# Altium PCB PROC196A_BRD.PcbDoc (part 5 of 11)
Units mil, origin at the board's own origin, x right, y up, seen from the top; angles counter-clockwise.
Board outline 3346.45 x 4921.26 mil, 8 copper layers (Top Layer, GND1, SIG1, PWR1, PWR2, SIG2, GND2, Bottom Layer), stack 54.534 mil thick; 736 components, 498 nets, 3030 pads, 1279 vias.
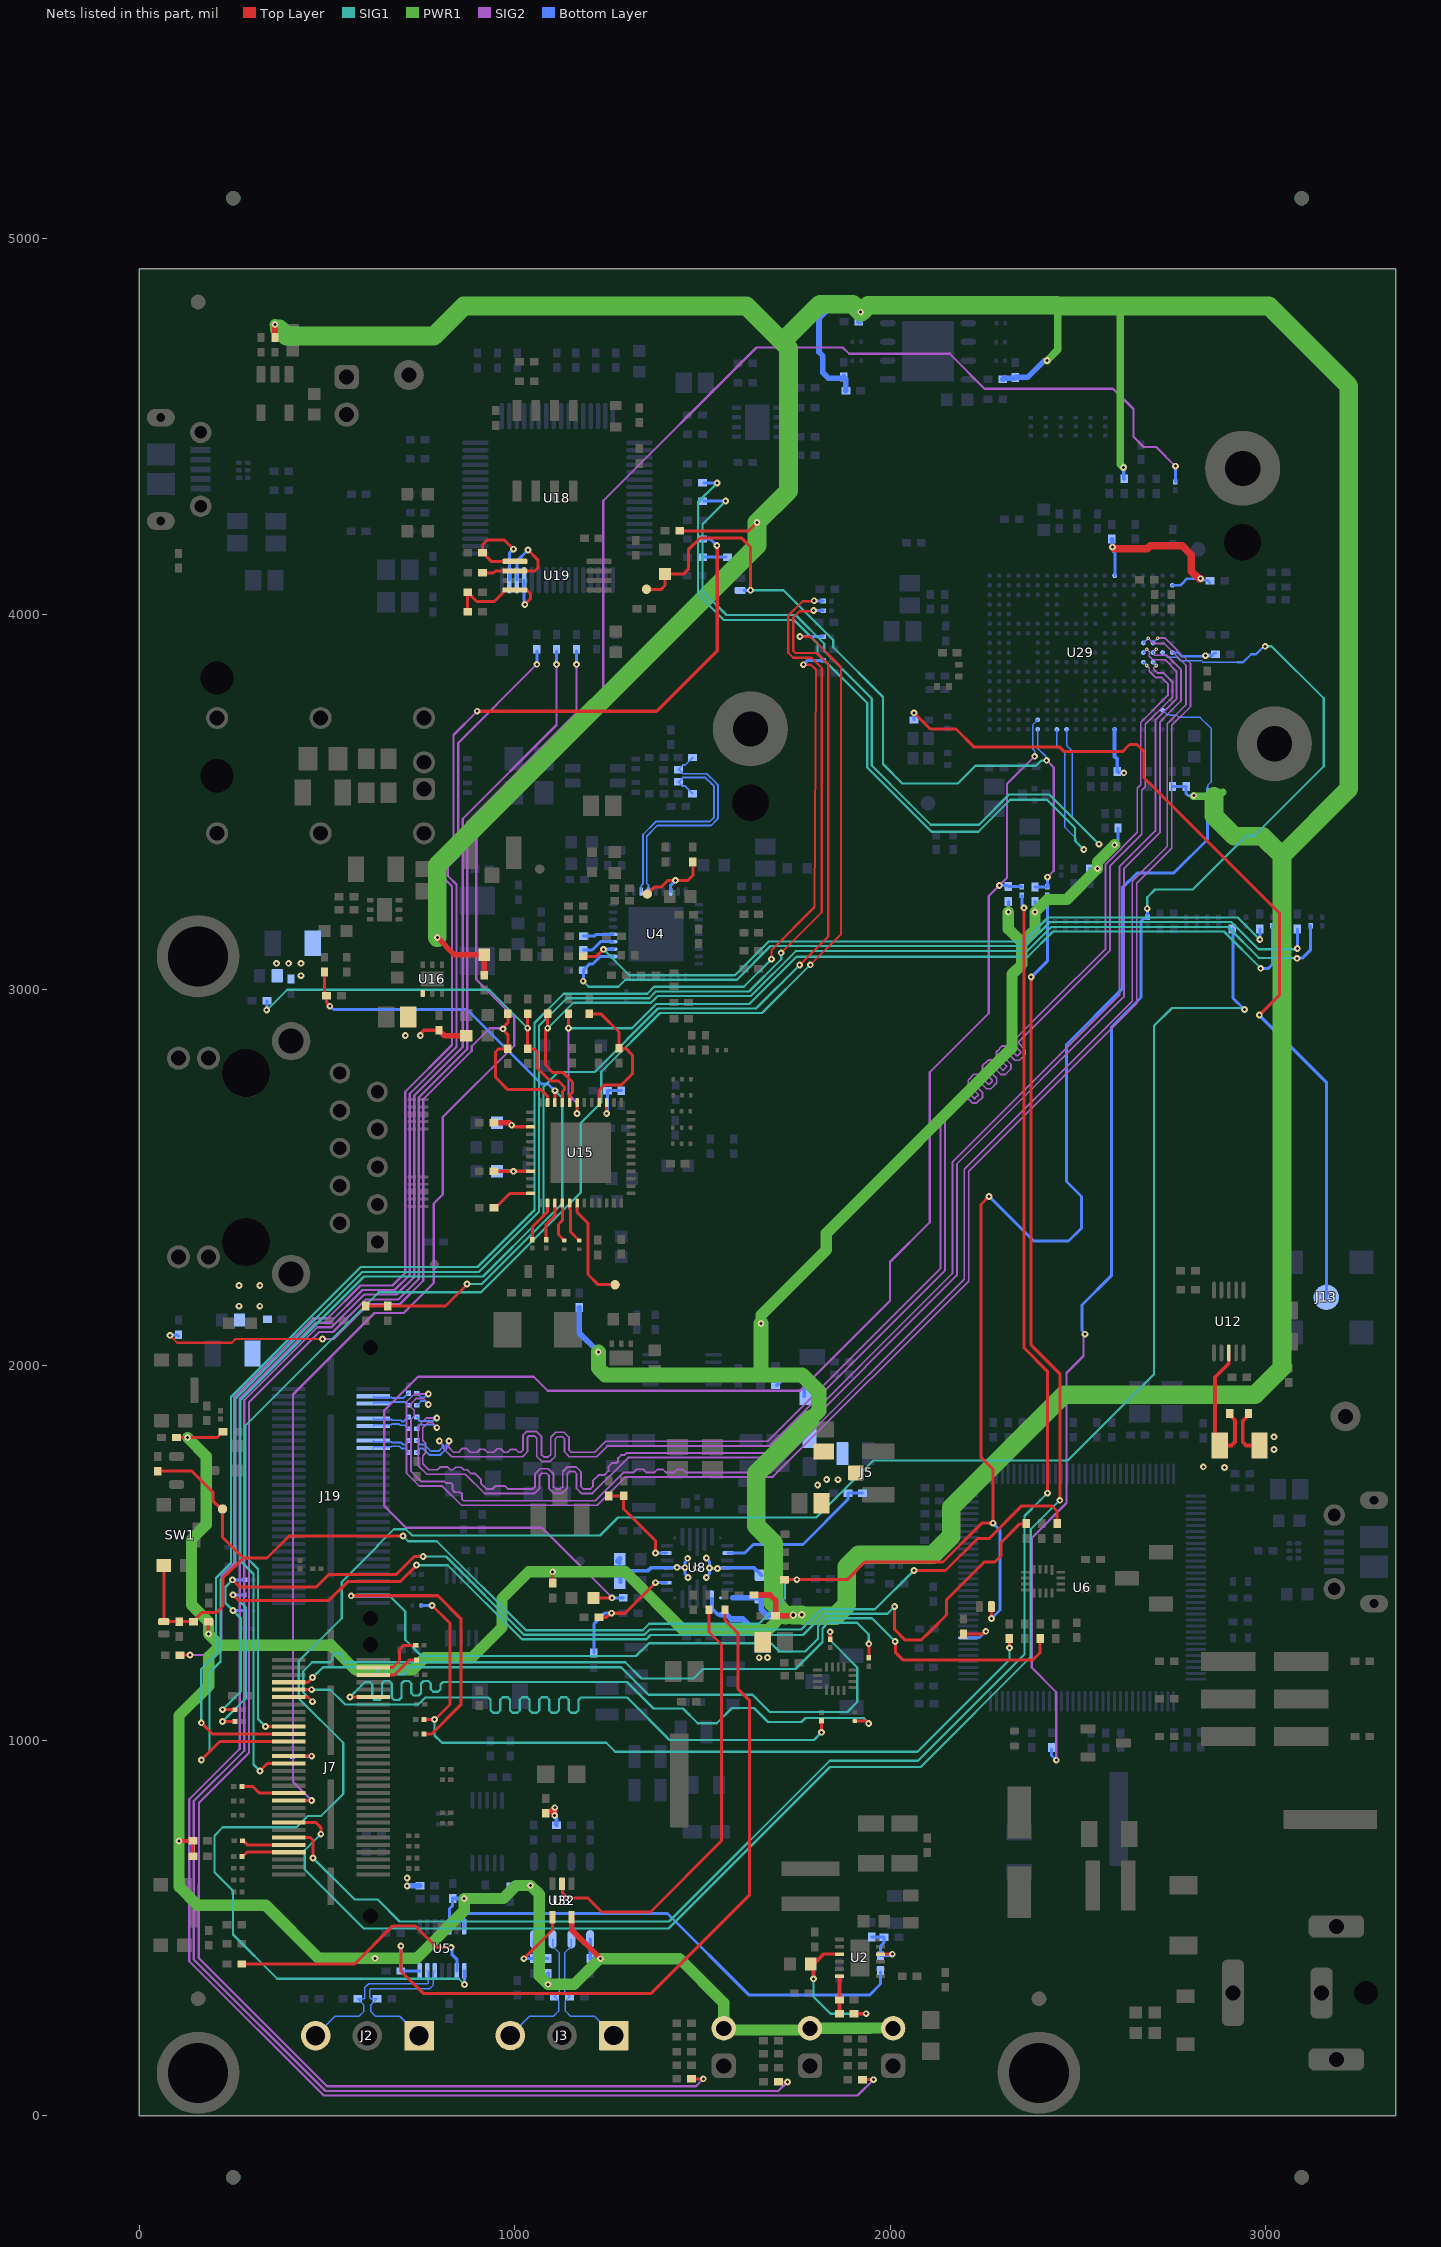
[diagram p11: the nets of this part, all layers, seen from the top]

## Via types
v1: diameter 18, hole 8, Top Layer to Bottom Layer, tented both sides, 1230 vias
v2: diameter 19.68, hole 7.87, Top Layer to Bottom Layer, 30 vias
v3: diameter 20, hole 10, Top Layer to Bottom Layer, tented both sides, 11 vias
v4: diameter 10, hole 4, SIG2 to Bottom Layer, tented both sides, 6 vias
v5: diameter 19.68, hole 7.87, Top Layer to Bottom Layer, tented both sides, 2 vias

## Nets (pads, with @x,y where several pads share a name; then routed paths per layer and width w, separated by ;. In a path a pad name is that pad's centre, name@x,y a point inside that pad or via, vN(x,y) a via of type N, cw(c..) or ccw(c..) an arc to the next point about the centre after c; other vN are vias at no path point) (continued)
1V8_FILTERED: C169.1 C194.1 C198.1 J5.1 R60.1 R65.1 R104.2 | length 114.6
  Bottom Layer w10: R65.1@1698.44,1946.4 1711.33,1959.29 1760.62,1959.29 1771.4,1948.52 R60.1@1771.4,1916.69
  other v1: 1807.21,1680.66 1831.14,1695.12 1861.42,1694.6
2V5_ETH: C34.1 C38.1 C59.1 C187.1 C188.1 C189.1 R293.2 U15.3 U15.9 U16.1 | length 398.4
  Top Layer w9: v1(991.92,2639.09) 994.36,2639.09 999.01,2634.44 U15.3@1042.07,2634.44 ; v1(997.01,2516.33) U15.9@1042.07,2516.33
  Top Layer w10: v1@748.4,2881.92 758.32,2891.84 C34.1@798.3,2891.84 ; C188.1@948.66,2516.33 v1(997.01,2516.33)
  Top Layer w15: C34.1@798.3,2891.84 812.92,2877.21 R293.2@870.42,2877.21 ; C189.1@944.72,2645.15 985.05,2645.15 991.11,2639.09 v1(991.92,2639.09)
  Bottom Layer w10: C59.1@956.53,2516.33 v1(997.01,2516.33) ; C187.1@956.53,2645.15 v1@987.04,2645.15
  other v1: 708.4,2877.92 748.4,2877.92
3V3: C174.2 C175.2 C176.2 C177.2 R346.2 R348.1 U12.8 U29.A14 U29.J20 U29.T20 U29.U14 | length 1163.4
  Top Layer w10: U12.8@2902.35,2032.4 2902.35,2004.12 2865.55,1967.32 2865.55,1794.63 2874.14,1786.04 R346.2@2878.07,1786.04 2909.57,1786.04 2918.92,1795.39 2918.92,1853.17 R348.1@2905.36,1866.74
  Top Layer w20: v1(2592.55,4179) 2596.55,4175 2684.82,4175 2692.82,4183 2777.85,4183 2802.7,4158.16 2802.7,4115.34 2823.04,4095 v1(2827.47,4095)
  Bottom Layer w6: U29.J20@2751.89,3898.25 2766.56,3898.25 2776.55,3888.26 2838.64,3888.26 v1(2840.2,3889.81) ; C176.2@2856.7,3890.12 2863.04,3896.46 C176.2@2868.04,3896.46
  Bottom Layer w7: v1(2592.55,4179) 2594.65,4176.9 2594.65,4167.2 2599.18,4162.68 2599.18,4138.07 2599.18,4127.7 2599.18,4104.17 U29.U14@2598,4102.99 ; U29.T20@2751.52,4077.38 2773.99,4077.38 2777.67,4081.06 2791.61,4095 2830.45,4095 2835.04,4090.41 2845.53,4090.41 C177.2@2851.87,4084.07
  Bottom Layer w10: U29.A14@2597.98,3693.52 2597.98,3621.48 2605.12,3614.33 C175.2@2605.12,3581.08 2606.68,3579.53 2621.25,3579.53 v1(2622.78,3578) ; v1@2840.5,3890.12 C176.2@2856.7,3890.12
  Bottom Layer w12: C174.2@2590.78,4200.46 2591.67,4199.57 2591.67,4179.88 v1(2592.55,4179)
  other v1: 2890.8,1727.02 2834.59,1728.9
3V3_VIO: C12.2 C20.2 J17.2 J18.2 J20.2 R18.1 R28.1 R37.1 R38.2 R41.2 R43.2 R49.2 R53.1 R106.2 R116.2 R177.1 R199.2 R261.2 R262.2 R263.2 R264.2 R271.2 R272.2 R273.2 R276.2 R277.2 R278.2 R279.2 R280.2 R295.2 R301.2 R309.2 R333.2 R346.1 R352.1 R409.2 U3.5 U5.5 U32.5 | length 21624.3
  Top Layer w8: R333.2@98.52,1807.13 v1(127.97,1807.13) 207.37,1807.13 R263.2@223.1,1822.86 ; R262.2@1100.93,1419.24 v1(1100.96,1449.11) ; R261.2@1439.69,4222.31 1623,4222.31 v1(1645.5,4244.81)
  Top Layer w10: v1(105.33,732.43) R276.2@142.44,732.43 R277.2@142.44,691.43 ; v1@183.82,1284.23 R264.2@183.82,1316.33 ; R352.1@2954.95,1866.86 2939.82,1851.73 2939.82,1794.25 2948.03,1786.04 R346.1@2978.54,1786.04
  Top Layer w15: R409.2@361.36,4737.7 v1(361.36,4772.2) ; v1(793.83,3138.78) 839.8,3092.81 R28.1@918.99,3092.81 R295.2@918.99,3038.71 ; U32.5@1151.52,529.29 1151.52,495.51 v1(1228.36,418.66) ; R106.2@1637.16,1387.47 1680.18,1387.47 1694.99,1372.67 R199.2@1694.99,1332.02 1738.38,1332.02 1740.36,1334 v3(1741.71,1334)
  PWR1 w20: v1(2418,4676) 2446.89,4704.89 2446.89,4821.18 ; 2612.88,4821.18 2612.88,4399.95 v1(2621.58,4391.26) ; v1@2806.98,3514.81 v1(2809.17,3517) 2811.36,3514.81 2862.65,3514.81 2874.11,3514.81 2886,3526.71
  PWR1 w30: v1(127.97,1807.13) 177.92,1757.17 177.92,1574.6 138.95,1535.63 138.95,1361.6 184.2,1316.35 v1(184.2,1283.85) 214.78,1253.27 ; v1(361.36,4772.2) 372.69,4760.87 ; v1(1656.27,2111) 1656.27,2132.75 1829.91,2306.39 1829.91,2350.9 2324.55,2845.54 2324.55,3041.23 2351,3067.68 2351,3125.86 ; 1721.25,1334 1714.41,1334 1675.41,1295 1448.69,1295 1294.59,1449.11 v1(1100.96,1449.11) 1037.1,1449.11 966.21,1378.22 966.21,1301.35 884.91,1220.05 759.41,1220.05 727.52,1188.16 576.21,1188.16 511.09,1253.27 214.78,1253.27 ; J20.2@2007.9,233.08 2007.9,233.71 1946.47,233.71 1945.84,233.08 1791.39,233.08 1786.64,228.34 1561.38,228.34 1556.83,232.88 J17.2@1556.83,233.08 1556.83,300.92 1439.08,418.66 v1(1228.36,418.66) 1226.72,418.66 1158.28,350.23 v1(1088.45,350.23) 1065.62,373.05 1065.62,590.2 v1(1042.17,613.65) 1003.93,613.65 969.36,579.09 v1(865.36,579.09) 865.36,546.41 738.48,419.53 v1(627.95,419.53) 478,419.53 336.72,560.81 155,560.81 105.33,610.48 v1(105.33,732.43) 105.33,1066.14 185,1145.81 185,1223.49 214.78,1253.27 ; v1(2314.95,3206.96) 2314.95,3161.92 2351,3125.86 ; v1(2598.26,3386) 2552.72,3340.46 v1(2552.72,3322.53) 2470.71,3240.52 2419.56,3240.52 v1(2386,3206.96) 2386,3160.86 2351,3125.86
  PWR1 w40: v1(1222.74,2034.89) 1222.74,1991.75 1240.3,1974.19 1656.27,1974.19 ; v1(1656.27,2111) 1656.27,1974.19 ; 1721.25,1334 v3(1741.71,1334) ; 1787.19,1854.76 1809.97,1877.54 1809.97,1929.65 1765.43,1974.19 1656.27,1974.19
  PWR1 w50: 372.69,4760.87 392.29,4741.26 784.23,4741.26 864.15,4821.18 1617.63,4821.18 1712.95,4725.86 ; v1(793.83,3138.78) 793.83,3331.64 1645.5,4183.31 v1(1645.5,4244.81) 1729.69,4329 1729.69,4709.12 1712.95,4725.86 ; 1721.25,1334 1689.65,1365.6 1689.65,1525.4 1643.23,1571.82 1643.23,1710.81 1787.19,1854.76 ; v3(1741.71,1334) 1763.95,1334 v3(1764.95,1335) 1767.93,1332.02 1855.05,1332.02 1884.34,1361.31 1884.34,1462.94 1916.08,1494.67 2113.3,1494.67 2162.88,1544.25 2162.88,1620.62 2463.26,1921 2972.19,1921 3044,1992.81 3044,3356.81 ; 2862.65,3514.81 2862.65,3463.24 2916.89,3409 2991.81,3409 3044,3356.81 ; 1712.95,4725.86 1813.09,4826 1900.61,4826 v1(1921.61,4805) 1923.43,4805 1942.09,4823.66 2444.41,4823.66 2446.89,4821.18 2612.88,4821.18 3009.63,4821.18 3222.15,4608.66 3222.15,3534.96 3044,3356.81
  Bottom Layer w8: U5.5@825.99,503.91 825.99,525.29 826.46,525.76 826.46,551.89 834.66,560.09 C12.2@834.66,579.09 ; v1@2314.95,3207.63 R271.2@2314.95,3235.34 ; v1(2386,3206.96) R272.2@2386,3234.67 ; v1(2598.26,3386) 2598.26,3388.71 2607.2,3397.65 2607.2,3430.39 R309.2@2607.16,3430.44 ; R279.2@2752.31,3541.71 R278.2@2788.54,3541.71 ; R278.2@2788.94,3541.2 2788.94,3522.32 2793.63,3517.63 2808.54,3517.63 v1(2809.17,3517)
  Bottom Layer w10: v1(627.95,419.53) R18.1@657.14,419.53 ; C12.2@834.66,579.09 v1(865.36,579.09) ; R53.1@987.9,613.65 v1(1042.17,613.65) ; v1(1088.45,350.23) R177.1@1088.45,379.29 ; U3.5@1200.93,470.24 C20.2@1200.93,418.66 v1(1228.36,418.66) ; R301.2@2531.76,3322.25 2532.04,3322.53 v1(2552.72,3322.53) ; v1(2621.58,4391.26) 2622.62,4390.22 2622.62,4362.14 R273.2@2623.66,4361.1
  Bottom Layer w15: R280.2@1171.49,2153.02 1171.49,2086.13 v1(1222.74,2034.89) ; R116.2@1713.65,1332.02 1714.67,1333.04 1740.75,1333.04 v3(1741.71,1334) ; R38.2@1882.26,4595.86 1882.26,4626.29 R49.2@1876.26,4632.29 1872.97,4629 1835.62,4629 1820.83,4643.79 1820.83,4688.34 1810.72,4698.45 1810.72,4787.96 1834.76,4812 1913.8,4812 1920.8,4805 v1(1921.61,4805) 1921.61,4804.19 1920.94,4803.52 1920.94,4781.63 1918.6,4779.29 R43.2@1916.63,4779.29 ; R37.1@2300.06,4626.23 2302.4,4628.58 2330.92,4628.58 2333.26,4630.92 R41.2@2333.26,4631.21 2366.04,4631.21 2410.25,4675.43 2417.43,4675.43 v1(2418,4676)
  other v1: 3023,1774.81 3023,1808.81
3V3REG_EN: R6.2 U5.7 | length 1275.1
  Bottom Layer w8: U5.7@865.36,503.91 865.36,533.17 871,538.81 1407.22,538.81 1624.52,321.51 1944.95,321.51 1974.33,350.89 R6.2@1974.33,383.23
3V3REG_ENA: R6.1 R7.2 R8.1 U2.10 | length 152
  Top Layer w8: U2.10@1974.33,430.47 v1(2005.93,430.47)
  Bottom Layer w8: R8.1@1950.73,476.14 R7.2@1984.19,476.14 1984.19,461.42 1974.33,451.56 R6.1@1974.33,426.54 2001.99,426.54 v1(2005.93,430.47)
3V3REG_MODE: R9.1 R10.2 U2.6 | length 99.7
  Top Layer w10: R9.1@1864.88,271.68 1864.88,285.53 R10.2@1864.88,308.55 U2.6@1864.88,371.42
3V3REG_VCC: C10.1 R9.2 U2.3 | length 357.8
  Top Layer w8: 1822.79,430.56 1823.02,430.78 1843.51,430.78 1843.51,430.47 U2.3@1864.88,430.47
  Top Layer w10: v1(1796.21,365.1) C10.1@1796.21,404.47 ; C10.1@1796.7,404.47 1822.79,430.56 1823.02,430.56 ; R9.2@1904.25,271.68 1935.92,271.68 v1(1936.33,272.1)
  SIG1 w6: v1(1796.21,365.1) 1796.21,317.38 1841.49,272.1 v1(1936.33,272.1)
5V0: C119.1 C120.1 R16.2 R78.2 R332.2 U8.10 | length 315
  Top Layer w15: R332.2@1082.76,806.12 1082.76,808.09 1085.1,810.43 1095.46,810.43 1106.03,821 v1(1106.84,821) ; v1(1106.32,800) 1106.84,800.52 v1@1106.84,815.96
  Bottom Layer w10: v1(1106.32,800) 1108.04,798.28 1108.04,796.49 1111.55,792.97 R78.2@1111.55,774.22 R78.2@1108.19,777.59 ; U8.10@1525.5,1376.58 1525.5,1350.98 1541.38,1335.1 1548.07,1335.1 ; C119.1@1660.85,1261.41 C119.1@1660.85,1270.18
  Bottom Layer w15: v1@715.7,612.55 R16.2@747.25,612.55 ; 1548.07,1335.1 1564.36,1335.1 1575.8,1323.66 1607.37,1323.66 C119.1@1660.85,1270.18
  other v1: 713.59,612.55 713.59,633.51 1651.19,1220.55 1673.49,1220.68
+3.3VD: C124.2 R116.1 U8.9 | length 132.6
  Bottom Layer w15: 1580.61,1379.84 1656.4,1379.84 C124.2@1657.09,1379.14 1657.09,1348.26 1673.33,1332.02 R116.1@1675.3,1332.02
AGND: C3.1 C123.1 C124.1 NT1.2 NT2.1 NT3.1 NT4.1 U8.5 U8.5-19 U8.19 | length 507.7
  Bottom Layer w8: U8.19@1409.35,1459.75 1410.05,1460.45 1431.63,1460.45 v1(1432.33,1461.15) 1432.64,1460.85 1452.63,1460.85 v1(1453.33,1460.15) ; v1(1460.93,1485.15) 1460.93,1483.03 1453.33,1475.43 v1(1453.33,1460.15) ; v1(1461.53,1434.35) 1461.53,1435.86 1453.33,1444.06 v1(1453.33,1460.15) ; v1(1510.53,1434.15) 1510.53,1435.46 1518.93,1443.86 v1(1518.93,1459.35) ; v1(1510.53,1485.95) 1510.53,1484.63 1518.93,1476.23 v1(1518.93,1459.35) ; U8.5@1562.9,1459.75 1562.2,1459.05 1540.62,1459.05 v1(1539.92,1458.35) 1539.61,1458.65 1519.62,1458.65 v1(1518.93,1459.35)
  Bottom Layer w10: C3.1@1279.98,1483.26 1279.98,1461.98 1289.6,1452.36 ; C123.1@1281.98,1421.26 1281.98,1444.73 1289.6,1452.36 ; U8.19@1409.35,1459.75 1362.77,1459.75 1355.38,1452.36 1289.6,1452.36 ; U8.5@1562.9,1459.75 1637.51,1459.75 C124.1@1657.09,1440.16
  Bottom Layer w15: C3.1@1274.74,1478.02 C3.1@1279.98,1483.26
  other v1: 1486.13,1459.75
AR_NERROUT: DS2.2 R76.1 R271.1 R379.1 U29.B6 | length 4317.2
  Top Layer w8: DS2.2@1210.1,1379.84 v1@1259.43,1379.84
  SIG2 w6: v1(1259.46,1379.87) 1072.47,1566.86 710.06,1566.86 652.44,1624.48 652.44,1879.25 742,1968.81 1051,1968.81 1088,1931.81 1759.75,1931.81 1999.5,2171.56 1999.5,2274.32 2105.57,2380.39 2105.57,2779.87 2262.76,2937.06 2262.76,3249.46 v1(2290.88,3277.57) 2291.09,3277.57 2311.7,3298.19 2311.7,3548.53 v1(2385.09,3621.93)
  Bottom Layer w4: v1(2385.09,3621.93) 2385.09,3636.13 2380.53,3640.69 2380.53,3706.39 U29.B6@2393.25,3719.11
  Bottom Layer w8: v1@1259.5,1379.84 R76.1@1289.24,1379.84 ; v1(2290.88,3277.57) 2291.13,3277.32 2312.34,3277.32 R271.1@2314.95,3274.71 2350.33,3274.71 R379.1@2351,3274.04
AR_NRST: C105.2 D2.2 D4.2 R99.1 R264.1 R266.1 SW1.4 TP4.1 U29.C19 | length 6359.5
  Top Layer w8: R266.1@49.46,1717.26 140.04,1717.26 196.49,1660.81 196.49,1637.49 221.49,1612.49 221.49,1541.07 276.57,1486 ; SW1.4@64.98,1452.25 D4.2@64.98,1316.33 C105.2@105.96,1316.33 R264.1@144.45,1316.33 144.45,1318.97 166.96,1341.47 205.94,1341.47 222.91,1358.44 222.91,1432.48 239.53,1449.11 239.68,1449.11 276.57,1486 ; v1(702.46,1544.91) 399.1,1544.91 340.19,1486 276.57,1486 ; v1(1751.63,1428.39) 1885.82,1428.39 1932.74,1475.31 2141.02,1475.31 2244.52,1578.81 v1(2274,1578.81) 2274,1722.16 2242,1754.16 2242,2427.69 v1(2263.73,2449.42) ; D2.2@2270.07,1356.5 2270.25,1356.32 v1(2270.25,1324.63)
  Top Layer w8.3: R99.1@1718.74,1428.39 v1(1751.63,1428.39)
  SIG1 w6: v1(702.46,1544.91) 716.37,1531 792.56,1531 1029.86,1293.7 1341.01,1293.7 1358.13,1310.81 1651.03,1310.81 1719.06,1378.85 1719.06,1415.5 1731.95,1428.39 v1(1751.63,1428.39)
  Bottom Layer w4: U29.C19@2725.93,3744.7 2738.76,3731.87 2746.36,3731.87 2746.4,3731.83 2763.15,3731.83 2769.48,3725.5 2825.77,3725.5 2854.95,3696.32 2854.95,3553.04 2845.65,3543.74 2845.65,3536.81
  Bottom Layer w8: v1(2263.73,2449.42) 2382.81,2330.34 2475.38,2330.34 2509.69,2364.66 2509.69,2449.35 2469.96,2489.08 2469.96,2853.77 2619.8,3003.61 2619.8,3273 2657.61,3310.81 2756,3310.81 2845.65,3400.46 2845.65,3536.81 ; v1(2270.25,1324.63) 2293,1347.38 2293,1559.81 v1(2274,1578.81)
AR_NRST_FTDI: R166.2 R268.1 | length 4018.4
  Top Layer w8: R268.1@108.28,1227 108.69,1227.4 134.59,1227.4 v1(135,1227.81)
  Top Layer w8.3: v1(899.92,3742.04) 900.15,3741.81 1378,3741.81 1539.43,3903.24 1539.43,4182.31 v1(1538.46,4183.28)
  SIG2 w6: v1(135,1227.81) 202.52,1227.81 219,1244.29 219,1438.81 252,1471.81 252,1913.39 463.42,2124.81 502.15,2124.81 589.34,2212 674.39,2212 708,2245.61 708,2727.88 833.08,2852.96 833.08,3275.33 809.69,3298.71 809.69,3336.55 836.62,3363.48 836.62,3678.74 v1(899.92,3742.04)
  Bottom Layer w8: R166.2@1503.74,4200.6 1521.14,4200.6 v1(1538.46,4183.28)
AR_NRST_XDS: R36.1 U6.40 | length 117.2
  Top Layer w7: R36.1@2194.69,1283.63 2245.4,1283.63 2252.58,1290.81 v1(2255,1290.81)
  Bottom Layer w7: U6.40@2208.34,1273.3 2208.5,1273.47 2236.8,1273.47 2254.14,1290.81 v1(2255,1290.81)
AR_SOP0_FTDI: R171.2 R308.2 | length 5983.6
  Top Layer w8: R308.2@1926.71,96.1 v1(1955.58,96.1)
  SIG2 w6: v1(1058.91,3867.06) 849.28,3657.43 849.28,3354.27 821.69,3326.68 821.69,3303.68 845.08,3280.3 845.08,2847.99 720,2722.91 720,2240.12 679.88,2200 594.31,2200 507.12,2112.81 468.96,2112.81 267.37,1911.22 267.37,977.7 133.19,843.52 133.19,411.62 491,53.81 1913.29,53.81 v1(1955.58,96.1)
  Bottom Layer w8: v1(1058.91,3867.06) R171.2@1058.91,3902.94
AR_SOP1_FTDI: R170.2 R304.2 | length 5720.1
  Top Layer w8: R304.2@1702.27,90.41 1702.43,90.25 1726.29,90.25 v1(1726.45,90.09)
  SIG2 w6: v1(1111.12,3867.06) 1111.12,3704.97 861.28,3455.13 861.28,2847.22 732,2717.94 732,2234.77 685.23,2188 599.28,2188 512.09,2100.81 473.93,2100.81 279.37,1906.25 279.37,972.73 145.19,838.55 145.19,416.59 495.97,65.81 1702.17,65.81 v1(1726.45,90.09)
  Bottom Layer w8: v1(1111.12,3867.06) R170.2@1111.12,3902.94
AR_SOP2_FTDI: R169.2 R298.2 | length 5496.8
  Top Layer w8: R298.2@1471.02,98.61 v1(1502.46,98.61)
  SIG2 w6: v1(1164.49,3867.06) 1164.49,3737.49 873.28,3446.28 873.28,2842.25 744,2712.97 744,2229.59 689.37,2174.96 603.21,2174.96 516.06,2087.81 479.31,2087.81 292.37,1900.86 292.37,967.18 237,911.81 236.84,911.81 159,833.97 159,615.81 158.19,615 158.19,420.56 499.94,78.81 1482.66,78.81 v1(1502.46,98.61)
  Bottom Layer w8: v1(1164.49,3867.06) R169.2@1164.49,3902.94
AR_WRMRST: D5.2 D9.2 R272.1 R371.1 TP1.1 U29.A6 | length 2145.8
  Top Layer w8: TP1.1@1351,4066.81 1390.5,4066.81 1400.32,4076.63 D9.2@1400.32,4107.81 1450.5,4107.81 1462.5,4119.81 1462.5,4171.81 1493.58,4202.89 1604.92,4202.89 1628.18,4179.63 v1(1628.18,4064.21)
  SIG1 w6: v1(1628.18,4064.21) 1715.84,4064.21 1848.39,3931.66 1848.39,3912.37 1980.93,3779.83 1980.93,3601.23 2032.61,3549.55 2180.22,3549.55 2227.53,3596.86 2236.05,3596.86 2236.1,3596.81 2388.95,3596.81 2402.55,3610.41 2416.37,3610.41 v1(2417.04,3611.07)
  SIG2 w6: v1(2417.04,3611.07) 2436,3592.11 2436,3316.67 v1(2419.01,3299.68)
  Bottom Layer w4: U29.A6@2393.25,3693.52 2393.25,3642.96 2414.48,3621.73 2414.48,3613.63 v1(2417.04,3611.07)
  Bottom Layer w8: D5.2@1610.48,4063.7 1610.74,4063.95 1627.93,4063.95 v1(1628.18,4064.21) ; R272.1@2386,3274.04 R371.1@2418.82,3274.04 2418.91,3274.14 2418.91,3299.59 v1(2419.01,3299.68)
AR_WRMRST_FTDI: R330.2 R362.1 | length 59.5
  Bottom Layer w8: R330.2@1503.76,4152.19 R362.1@1563.24,4152.19
BSS_UARTA_TX: R131.1 R232.2 U29.J19 | length 3811.4
  SIG1 w6: v1(2685,3215.81) 2685,3246.46 2705.54,3267 2806.6,3267 2949.75,3410.15 2969.9,3410.15 3154.97,3595.22 3154.97,3776.33 3016.3,3915 v1(2999.33,3915)
  SIG2 w6: v1(2442.69,947.36) 2442.69,1128.62 2377.21,1194.1 2377.21,1539.56 2470,1632.35 2470,1639.81 2470,1979.09 2515.14,2024.23 2515.14,2074.77 2519.29,2078.93 v1(2519.29,2082.18)
  Bottom Layer w4: U29.J19@2725.93,3898.25 2738.65,3885.52 2764.32,3885.52 2773.16,3876.68 2829.28,3876.68 2833.74,3872.23 2925.19,3872.23
  Bottom Layer w6: 2925.19,3872.23 2938.88,3872.23 2940.3,3872.23 2962.07,3894 2975.08,3894 2996.08,3915 v1(2999.33,3915)
  Bottom Layer w8: R131.1@2430.04,977.32 2430.04,960.01 v1(2442.69,947.36) ; v1(2519.29,2082.18) 2519.29,2083.85 2511.28,2091.86 2511.28,2159.87 2589.21,2237.8 2589.21,2899.64 2668.7,2979.13 2668.7,3182.41 2676.02,3189.72 2683.7,3189.72 2686,3192.02 R232.2@2686,3192.81 2685.5,3193.31 2685.5,3215.31 v1(2685,3215.81)
CAN_nFAULT: R233.2 U5.8 | length 5868.7
  SIG1 w6: v1(865.9,349.81) 850.89,364.82 367.56,364.82 249.37,483.01 249.37,599.69 200.05,649.01 200.05,746.31 222.15,768.42 418.6,768.42 449.22,799.04 484.31,799.04 542.87,857.6 542.87,993.98 424.81,1112.04 424.81,1211.62 539.04,1325.85 539.04,1421.86 635.02,1517.85 635.02,1519.9 678.03,1562.91 709.92,1562.91 726.83,1546 1227,1546 1275.1,1594.1 1803.34,1594.1 1955.05,1745.81 2473.46,1745.81 2703.33,1975.68 2703.33,2903.8 2751.04,2951.51 2936.23,2951.51 2940.73,2947 v1(2943.98,2947)
  Bottom Layer w8: U5.8@865.36,385.8 865.63,385.53 865.63,350.07 v1(865.9,349.81) ; R233.2@2912,3162.1 2913,3161.1 2913,2977.98 v1(2943.98,2947)
CAN_WAKE: R55.1 U5.9 | length 689.2
  Top Layer w8: R55.1@276.53,404.47 573.66,404.47 675.19,506 734.43,506 791.43,449 v1(830.65,449)
  Bottom Layer w8: v1(830.65,449) 832.56,447.09 832.56,430.22 845.68,417.1 U5.9@845.68,385.8
CANA_N: J3.1 R87.1 U3.6 | length 367
  Bottom Layer w4: U3.6@1150.93,470.24 1150.93,451.92 1132.68,433.67 1132.68,367.25 1132.68,327.75 1135.02,325.41 1138.53,325.41 R87.1@1146.38,317.57 1134.93,306.12 1134.93,279.07 1148.92,265.09 1212.45,265.09 J3.1@1263.73,213.81
CANA_NSTB: R13.1 U32.2 | length 1177.4
  Top Layer w8: U32.2@1125.93,617.88 1126.65,617.15 1126.65,594.17 1140.82,580 1194.84,580 1231.84,543 1361.42,543 1550.99,732.57 1550.99,1255.73 1517.62,1289.1 R13.1@1517.62,1348.1
CANA_P: J3.3 R85.2 U3.7 | length 367
  Bottom Layer w4: J3.3@988.14,213.81 1039.41,265.09 1102.94,265.09 1116.93,279.07 1116.93,306.13 R85.2@1105.49,317.57 1113.33,325.42 1116.84,325.42 1119.18,327.76 1119.18,360.5 1119.18,433.83 1100.93,452.08 U3.7@1100.93,470.24
CANA_STB: R86.1 R177.2 U3.8 U32.4 | length 258.2
  Top Layer w8: v1(1024.06,418.66) 1100.33,494.94 U32.4@1100.33,529.29
  Bottom Layer w8: v1(1024.06,418.66) R86.1@1050.93,418.66 ; U3.8@1050.93,470.24 R86.1@1050.93,418.66 ; R177.2@1088.45,418.66 R86.1@1050.93,418.66
CANB_N: J2.1 R24.1 U5.12 | length 451
  Bottom Layer w4: J2.1@745.14,213.43 693.48,265.09 629.21,265.09 616.34,277.95 616.34,295.36 R24.1@632.93,311.94 616.44,311.94 614.09,314.29 614.09,336.05 616.44,338.39 773.28,338.39 783.53,348.64 783.53,382.71 U5.12@786.62,385.8
CANB_NSTB: R17.1 R18.2 R19.1 U5.14 | length 2032.8
  Top Layer w8: v1(696.51,452.4) 696.51,385.8 756.16,326.16 1363.56,326.16 1624.94,587.54 1624.94,1106.89 1595.36,1136.47 1595.36,1285.11 1560.12,1320.35 R17.1@1560.12,1348.1
  Bottom Layer w8: v1(696.51,452.4) R18.2@696.51,419.53 R19.1@696.51,385.8 U5.14@747.25,385.8
CANB_P: J2.3 R15.2 U5.13 | length 451
  Bottom Layer w4: J2.3@469.55,213.43 521.21,265.09 585.48,265.09 598.34,277.95 598.34,295.36 R15.2@581.76,311.94 598.25,311.94 600.59,314.29 600.59,341.64 610.84,351.89 767.69,351.89 770.03,354.23 770.03,382.71 U5.13@766.94,385.8
CLKP_SMA: J13.1 R269.2 | length 2390.4
  Top Layer w8: v1(2063.49,3737.81) 2106.83,3694.47 2175.53,3694.47 2224,3646 2452.11,3646 2464.11,3634 2618.97,3634 2625,3640.03 2630,3645.03 2638.01,3653.04 2657.96,3653.04 2677,3634 2677,3564 2704.19,3536.81 3036.85,3204.15 3036.85,2985.6 v1(2983.58,2932.33)
  Bottom Layer w8: R269.2@2063.49,3718.43 v1(2063.49,3737.81) ; v1(2983.58,2932.33) 3162.24,2753.66 J13.1@3162.24,2180.42
CSI2_0_N: J19.58 R192.2 R196.1 | length 101
  Bottom Layer w4.8: J19.58@623.08,1916.88 626.18,1913.79 671.38,1913.79 673.03,1912.14 703.41,1912.14 716.08,1924.8 R196.1@716.86,1924.8
CSI2_0_P: J19.56 R191.2 | length 99.3
  Bottom Layer w4.8: J19.56@623.08,1897.19 626.18,1900.28 671.38,1900.28 673.03,1901.94 707.44,1901.94 716.08,1893.3 R191.2@716.86,1893.3
CSI2_1_N: J19.52 R189.2 | length 101.9
  Bottom Layer w4.8: J19.52@623.08,1857.82 626.18,1854.73 671.38,1854.73 673.03,1853.08 696.48,1853.08 699.55,1850.01 704.28,1850.01 716.08,1861.81 R189.2@716.86,1861.81
CSI2_1_P: J19.50 R168.2 | length 101
  Bottom Layer w4.8: J19.50@623.08,1838.14 626.18,1841.23 671.38,1841.23 673.03,1842.88 692.25,1842.88 695.32,1839.81 706.58,1839.81 716.08,1830.31 R168.2@716.86,1830.31
CSI2_CLK_N: J19.46 R138.2 | length 104.9
  Bottom Layer w4.8: J19.46@623.08,1798.77 626.18,1795.68 671.38,1795.68 673.03,1794.02 696.66,1794.02 702.51,1788.17 709.37,1788.17 712.18,1790.98 712.18,1794.92 716.08,1798.82 R138.2@716.86,1798.82
CSI2_CLK_P: J19.44 R135.2 | length 104.9
  Bottom Layer w4.8: J19.44@623.08,1779.08 626.18,1782.17 671.38,1782.17 673.03,1783.82 692.43,1783.82 698.29,1777.97 709.37,1777.97 712.18,1775.16 712.18,1771.22 716.08,1767.32 R135.2@716.86,1767.32
CSI2_RX0_0_N: R192.1 U29.K18 | length 4099.8
  SIG2 w4.8: v1(769.8,1923.05) 732.25,1923.05 711.58,1902.39 711.58,1712.26 746.33,1677.51 807.3,1677.51 858.09,1626.72 1219.85,1626.72 1295.35,1702.21 1687.78,1702.21 2209.37,2223.8 2209.37,2516.62 2657.16,2964.41 2657.16,3283.52 2750.31,3376.67 2750.31,3704.09 2800.37,3754.15 2800.37,3869.11 2734.74,3934.73 2732.84,3936.63 v4(2713.14,3936.63)
  Bottom Layer w4.8: R192.1@738.91,1924.8 739.7,1924.8 750.35,1914.15 760.39,1914.15 769.29,1923.05 v1(769.8,1923.05) ; U29.K18@2700.34,3923.84 v4(2713.14,3936.63)
CSI2_RX0_0_P: R191.1 U29.K17 | length 4101.6
  SIG2 w4.8: v1@769.69,1895.16 769.69,1898.35 756.99,1911.05 737.22,1911.05 723.58,1897.41 723.58,1888.16 732.05,1879.69 732.05,1864.29 723.58,1855.82 723.58,1717.23 751.3,1689.51 812.64,1689.51 816.29,1685.86 829.28,1685.86 834.13,1681.01 834.13,1668.02 840.7,1661.46 855.3,1661.46 859.26,1657.49 859.26,1642.9 863.44,1638.72 1214.88,1638.72 1290.38,1714.21 1317.24,1714.21 1325.25,1722.22 1341.7,1722.22 1349.71,1714.21 1372.4,1714.21 1380,1721.81 1395,1721.81 1402.6,1714.21 1425.29,1714.21 1432.89,1721.81 1447.89,1721.81 1455.49,1714.21 1682.81,1714.21 2197.37,2228.77 2197.37,2521.59 2645.16,2969.39 2645.16,3288.5 2738.31,3381.64 2738.31,3709.06 2788.37,3759.12 2788.37,3864.14 2729.77,3922.73 2701.45,3922.73 v4(2687.55,3936.63)
  Bottom Layer w4.8: R191.1@738.91,1893.3 739.7,1893.3 750.35,1903.95 760.39,1903.95 769.29,1895.05 v1(769.8,1895.05) ; U29.K17@2674.75,3923.84 v4(2687.55,3936.63)
CSI2_RX0_1_N: R189.1 U29.J18 | length 4092.4
  SIG2 w4.8: v1(792.39,1859.06) 764.26,1859.06 743,1837.8 743,1732.25 766.34,1708.91 868.71,1708.91 919.51,1658.12 1052.89,1658.12 1066.12,1671.35 1066.12,1705.7 1072.32,1711.9 1084.72,1711.9 1090.92,1705.7 1090.92,1671.35 1104.14,1658.12 1126.49,1658.12 1139.72,1671.35 1139.72,1710.47 1145.92,1716.67 1158.32,1716.67 1164.52,1710.47 1164.52,1671.35 1177.74,1658.12 1206.85,1658.12 1302.14,1753.41 1692.42,1753.41 2177.97,2238.96 2177.97,2535.72 2622.97,2980.72 2622.97,3322.29 2718.91,3418.22 2718.91,3713.3 2774.81,3769.2 2774.81,3853.74 2769.55,3859 2737.55,3891 2704.67,3891 2702.34,3893.33 2702.34,3900.25 v4(2709.14,3907.04)
  Bottom Layer w4.8: R189.1@738.91,1861.81 739.7,1861.81 743.6,1857.91 743.6,1853.97 746.41,1851.16 782.98,1851.16 790.88,1859.06 v1(792.39,1859.06) ; U29.J18@2700.34,3898.25 v4(2709.14,3907.04)
CSI2_RX0_1_P: R168.1 U29.J17 | length 4091.1
  SIG2 w4.8: v1(792.39,1833.06) 792.39,1834.45 779.78,1847.06 769.23,1847.06 755,1832.83 755,1799.31 762,1792.31 762,1765.4 755,1758.4 755,1737.22 771.31,1720.91 793.91,1720.91 801.3,1728.3 821.04,1728.3 828.43,1720.91 835.5,1720.91 842.59,1728 857.31,1728 864.4,1720.91 873.69,1720.91 883.6,1711 894.31,1711 909.97,1695.34 909.97,1684.62 924.48,1670.12 941.5,1670.12 949.58,1678.2 973.39,1678.2 981.47,1670.12 1047.92,1670.12 1054.12,1676.32 1054.12,1710.67 1067.34,1723.9 1089.69,1723.9 1102.92,1710.67 1102.92,1676.32 1109.12,1670.12 1121.52,1670.12 1127.72,1676.32 1127.72,1715.44 1140.94,1728.67 1163.29,1728.67 1176.52,1715.44 1176.52,1676.32 1182.72,1670.12 1201.88,1670.12 1208.28,1676.53 1208.28,1691.77 1223.51,1707 1238.76,1707 1249.78,1718.02 1249.78,1729.61 1259.17,1739 1270.76,1739 1275.24,1743.48 1275.24,1752.34 1283.19,1760.29 1292.05,1760.29 1297.17,1765.41 1687.45,1765.41 2165.97,2243.93 2165.97,2540.69 2610.97,2985.69 2610.97,3327.26 2706.91,3423.19 2706.91,3718.27 2762.81,3774.17 2762.81,3848.77 2732.58,3879 2699.7,3879 2696.18,3882.51 2690.34,3888.36 2690.34,3900.25 v4(2683.55,3907.04)
  Bottom Layer w4.8: R168.1@738.91,1830.31 739.7,1830.31 743.6,1834.21 743.6,1838.15 746.41,1840.96 782.98,1840.96 790.88,1833.06 v1(792.39,1833.06) ; U29.J17@2674.75,3898.25 v4(2683.55,3907.04)
CSI2_RX0_CLK_N: R138.1 U29.H18 | length 4098.5
  SIG2 w4.8: v1(799,1797.81) 811.66,1785.15 811.66,1776.08 831.93,1755.81 1020.89,1755.81 1034.12,1769.04 1034.12,1808.53 1036.93,1811.34 1052.72,1811.34 1058.92,1805.14 1058.92,1756.53 1072.14,1743.3 1094.49,1743.3 1107.72,1756.53 1107.72,1803.05 1113.92,1809.25 1126.32,1809.25 1132.52,1803.05 1132.52,1769.04 1145.74,1755.81 1218.39,1755.81 1247.39,1784.81 1678.83,1784.81 2146.57,2252.55 2146.57,2665.29 2174.16,2692.88 2197.29,2716.01 2201.27,2716.01 2218.93,2698.35 2230.96,2698.35 2246.36,2713.75 2246.36,2725.79 2219.99,2752.16 2219.99,2754.26 2228.36,2762.63 2230.45,2762.63 2256.83,2736.25 2268.86,2736.25 2284.27,2751.66 2284.27,2763.69 2257.89,2790.07 2257.89,2792.16 2266.26,2800.53 2268.35,2800.53 2294.73,2774.15 2306.76,2774.15 2322.17,2789.56 2322.17,2801.59 2295.79,2827.97 2295.79,2830.06 2304.16,2838.43 2306.26,2838.43 2332.63,2812.05 2344.67,2812.05 2360.07,2827.46 2360.07,2839.49 2342.41,2857.15 2342.41,2861.13 2431.47,2950.19 2586,3104.72 2586,3329.72 2670.6,3414.32 2670.6,3531.84 2675.57,3536.81 2679.78,3541.02 2679.78,3658.75 2679.78,3661.86 2679.78,3706.86 2744.66,3771.74 2752.01,3779.09 2752.01,3819.93 2728.02,3843.92 2711.82,3843.92 2702.34,3853.4 2702.34,3857.38 2708.82,3863.86 v4(2709.14,3863.86)
  Bottom Layer w4.8: R138.1@738.91,1798.82 739.7,1798.82 743.6,1794.92 743.6,1790.98 746.41,1788.17 759.6,1788.17 776.96,1770.81 797.77,1770.81 807.66,1780.7 807.66,1787.72 799,1796.37 v1(799,1797.81) ; U29.H18@2700.34,3872.66 v4(2709.14,3863.86)
CSI2_RX0_CLK_P: R135.1 U29.H17 | length 4099.1
  SIG2 w4.8: v1(825,1797.81) 823.66,1796.47 823.66,1781.05 836.9,1767.81 850.42,1767.81 860.61,1778 871.46,1778 881.65,1767.81 900.19,1767.81 908.38,1776 919.21,1776 927.4,1767.81 944.55,1767.81 953.74,1777 962.61,1777 971.8,1767.81 980.94,1767.81 988.13,1775 1003.38,1775 1010.57,1767.81 1015.92,1767.81 1022.12,1774.01 1022.12,1813.5 1031.96,1823.34 1057.69,1823.34 1070.92,1810.11 1070.92,1761.5 1077.12,1755.3 1089.52,1755.3 1095.72,1761.5 1095.72,1808.02 1108.94,1821.25 1131.29,1821.25 1144.52,1808.02 1144.52,1774.01 1150.72,1767.81 1213.42,1767.81 1242.42,1796.81 1673.86,1796.81 2134.57,2257.52 2134.57,2670.26 2165.67,2701.36 2192.32,2728.01 2206.24,2728.01 2223.9,2710.35 2225.99,2710.35 2234.36,2718.72 2234.36,2720.82 2207.99,2747.19 2207.99,2759.23 2223.39,2774.63 2235.42,2774.63 2261.8,2748.25 2263.89,2748.25 2272.27,2756.63 2272.27,2758.72 2245.89,2785.1 2245.89,2797.13 2261.29,2812.53 2273.32,2812.53 2299.7,2786.15 2301.79,2786.15 2310.17,2794.53 2310.17,2796.62 2283.79,2823 2283.79,2835.03 2299.19,2850.43 2311.23,2850.43 2337.6,2824.05 2339.7,2824.05 2348.07,2832.43 2348.07,2834.52 2330.41,2852.18 2330.41,2866.1 2422.99,2958.68 2574,3109.69 2574,3334.69 2658.6,3419.29 2658.6,3536.81 2667.78,3545.99 2667.78,3658.75 2667.78,3661.86 2667.78,3711.83 2740.01,3784.06 2740.01,3814.96 2723.05,3831.92 2706.85,3831.92 2690.34,3848.43 2690.34,3857.38 2683.86,3863.86 v4(2683.55,3863.86)
  Bottom Layer w4.8: R135.1@738.91,1767.32 739.7,1767.32 743.6,1771.22 743.6,1775.16 746.41,1777.97 755.37,1777.97 772.73,1760.61 802,1760.61 817.86,1776.47 817.86,1788.4 825,1795.54 v1(825,1797.81) ; U29.H17@2674.75,3872.66 v4(2683.55,3863.86)
DBG_EPWMA0: J7.6 R81.2 | length 127.5
  Top Layer w8: J7.6@623.08,1174.67 679.55,1174.67 718.92,1214.04 R81.2@734.26,1214.04
DBG_GPADC1: J7.19 R80.2 | length 4087.9
  Top Layer w6: v1(1759.43,3940.81) 1760.12,3940.12 1788.76,3940.12 1869,3859.88 1869,3147.97 v1(1787.42,3066.4)
  Top Layer w8: v1(336.18,1036.88) J7.19@397.49,1036.88
  SIG1 w6: v1(336.18,1036.88) 316,1057.06 316,1456.67 282.02,1490.65 282.02,1838.19 637.95,2194.12 910.43,2194.12 1176,2459.7 1176,2644.89 1230.74,2699.64 1230.74,2781.61 1386.94,2937.81 1658.84,2937.81 v1(1787.42,3066.4)
  Bottom Layer w8: v1(1759.43,3940.81) 1759.87,3940.37 R80.2@1821.1,3940.37
DBG_GPADC2: J7.21 R82.2 | length 4276.6
  Top Layer w6: v1(1683.77,3081.25) 1683.77,3105.19 1798.79,3220.21 1802.89,3845.5 ccw(c1785.89,3845.61) 1802.79,3847.43 1802.29,3852.05 1799.51,3855.78 ccw(c1785.89,3845.61) 1797.03,3858.45 1788.47,3865.88 v1(1768.73,3865.88)
  Top Layer w8: v1(165.06,1046.87) 194.73,1017.19 J7.21@397.49,1017.19 J7.21@397.18,1016.88
  SIG1 w6: v1(165.06,1046.87) 165.06,1190.1 204.1,1229.14 204.1,1432.91 244,1472.81 244,1915.04 590.02,2261.07 900.53,2261.07 1052.65,2413.19 1052.65,2911.46 1130.58,2989.39 1352.87,2989.39 1371.15,3007.66 1610.18,3007.66 v1(1683.77,3081.25)
  Bottom Layer w8: v1(1768.73,3865.88) 1780.5,3877.65 1821.61,3877.65 R82.2@1821.76,3877.49
DBG_GPADC3: J7.23 R83.2 | length 4617.1
  Top Layer w6: v1(1709.95,3098.38) 1818,3206.43 1818,3856.81 1790.53,3884.28 1742.26,3884.28 1729,3897.54 1729,3996.81 1767,4034.81 1796.32,4034.81 v1(1797.75,4036.24)
  Top Layer w8: v1(165.06,948.05) 214.48,997.48 352.5,997.48 ; 352.53,997.51 J7.23@397.49,997.51
  SIG1 w6: v1(165.06,948.05) 187.05,970.04 187.05,1181.22 216.1,1210.28 216.1,1427.81 256,1467.71 256,1910.07 593.74,2247.81 904.24,2247.81 1064.96,2408.53 1064.96,2904.02 1138.32,2977.39 1358.12,2977.39 1375.76,2995.02 1624.15,2995.02 1709.95,3080.82 v1(1709.95,3098.38)
  Bottom Layer w8: v1(1797.75,4036.24) 1798.15,4035.84 1821.36,4035.84 R83.2@1821.76,4035.43
DBG_GPADC5: J7.27 R91.2 | length 112.7
  Top Layer w8: J7.27@397.49,958.14 v1@458.81,958.14
  Bottom Layer w8: R91.2@408.15,957.34 458.41,957.34 v1(459.21,958.14)
DBG_GPADC6: J7.29 R94.2 | length 4381.6
  Top Layer w6: v1(1759,3065.81) 1835,3141.81 1835,3866.09 1803.81,3897.28 1747.65,3897.28 1742,3902.93 1742,3991.43 1758.95,4008.38 1794.49,4008.38 v1(1796.39,4010.27)
  Top Layer w8: v1(321.24,918.77) 340.93,938.45 J7.29@397.49,938.45
  SIG1 w6: v1(321.24,918.77) 304,936.01 304,1443.48 269.3,1478.18 269.3,1906.4 598.71,2235.81 915.14,2235.81 1076.96,2397.62 1076.96,2741.99 1115.65,2780.68 1212.84,2780.68 1381.97,2949.81 1643,2949.81 v1(1759,3065.81)
  Bottom Layer w8: v1(1796.39,4010.27) 1796.79,4009.86 1821.36,4009.86 R94.2@1821.76,4009.45
DBG_I2CA_SCL: J7.51 R390.2 | length 125.2
  Top Layer w8: R390.2@276.62,732.43 287.13,721.92 J7.51@397.49,721.92
DBG_I2CA_SDA: J7.53 R391.2 | length 126.8
  Top Layer w8: R391.2@275.33,690.95 286.62,702.23 J7.53@397.49,702.23
DBG_NERROUT: J7.49 R379.2 | length 4450.7
  Top Layer w8: J7.49@397.49,741.6 455.05,741.6 462.68,733.98 v1(462.68,687.08) ; v1(2356.62,3218.21) 2357,3217.83 2357,2045.86 2419,1983.86 v1(2419,1658.81)
  SIG1 w6: v1(462.68,687.08) 573.8,575.96 635.17,575.96 693.28,517.84 1411.21,517.84 1839.18,945.81 2074.46,945.81 2358,1229.35 2358,1597.81 2400,1639.81 v1(2419,1658.81)
  Bottom Layer w8: R379.2@2351,3251.21 2351,3226.54 2356.62,3220.91 v1(2356.62,3218.21)
DBG_SPI_CLK: J7.9 R399.2 | length 1864.1
  Top Layer w8: J7.9@397.49,1135.3 v1@458.81,1135.3 ; v1(1817.43,1021.8) R399.2@1817.43,1050.54
  SIG1 w6: v1(459.21,1135.3) 508.5,1135.3 548.18,1095.62 742.89,1095.62 761.66,1114.38 900.14,1114.38 929.14,1114.38 935.64,1107.88 935.64,1080.41 942.14,1073.91 955.14,1073.91 961.64,1080.41 961.64,1108.85 968.14,1115.35 981.14,1115.35 987.64,1108.85 987.64,1080.41 994.14,1073.91 1007.14,1073.91 1013.64,1080.41 1013.64,1108.85 1020.14,1115.35 1033.14,1115.35 1039.64,1108.85 1039.64,1080.41 1046.14,1073.91 1059.14,1073.91 1065.64,1080.41 1065.64,1108.85 1072.14,1115.35 1085.14,1115.35 1091.64,1108.85 1091.64,1080.41 1098.14,1073.91 1111.14,1073.91 1117.64,1080.41 1117.64,1108.85 1124.14,1115.35 1137.14,1115.35 1143.64,1108.85 1143.64,1080.41 1150.14,1073.91 1163.14,1073.91 1169.64,1080.41 1169.64,1107.88 1176.14,1114.38 1191.49,1114.38 1299.55,1114.38 1412.58,1001.35 1796.98,1001.35 v1(1817.43,1021.8)
DBG_SPI_CS0: J7.7 R223.2 | length 1875.9
  Top Layer w8: J7.7@397.49,1154.99 448.98,1154.99 v1(461.49,1167.5) ; R223.2@1840.26,1271.7 v1@1840.26,1289.37
  SIG1 w6: v1(461.49,1167.5) 488.9,1194.91 598.29,1194.91 627.29,1194.91 633.79,1188.41 633.79,1181.83 640.29,1175.33 653.29,1175.33 659.79,1181.83 659.79,1189.92 666.29,1196.42 679.29,1196.42 685.79,1189.92 685.79,1182.85 692.29,1176.35 705.29,1176.35 711.79,1182.85 711.79,1188.41 718.29,1194.91 738,1194.91 1283.3,1194.91 1356.18,1122.03 1633.45,1122.03 1679.58,1075.89 1886.52,1075.89 1912.75,1102.13 1912.75,1194.4 1840.23,1266.91 1840.23,1289.34 v1(1840.29,1289.4)
DBG_SPI_MISO: J7.12 R377.1 | length 1858
  Top Layer w8: v1@561.77,1115.62 J7.12@623.08,1115.62 ; R377.1@1906.18,1051.55 1936.96,1051.55 v1(1943.12,1045.39)
  SIG1 w6: v1(561.37,1115.62) 591.18,1145.43 601.47,1155.72 613.68,1155.72 620.18,1149.22 620.18,1114.12 626.68,1107.62 639.68,1107.62 646.18,1114.12 646.18,1151.89 652.68,1158.39 665.68,1158.39 672.18,1151.89 672.18,1114.12 678.68,1107.62 691.68,1107.62 698.18,1114.12 698.18,1151.89 704.68,1158.39 717.68,1158.39 724.18,1151.89 724.18,1126.38 730.68,1119.88 743.68,1119.88 750.18,1126.38 750.18,1151.89 756.68,1158.39 769.68,1158.39 776.18,1151.89 776.18,1136.35 782.68,1129.85 795.68,1129.85 802.18,1136.35 802.18,1149.22 808.68,1155.72 822.9,1155.72 1298.92,1155.72 1369.64,1085 1448.45,1085 1487.54,1045.9 1538.5,1045.9 1578.87,1086.27 1637.69,1086.27 1674.96,1049 1763.93,1049 1774.52,1059.58 1928.93,1059.58 v1(1943.12,1045.39)
DBG_SPI_MOSI: J7.11 R188.2 | length 1883
  Top Layer w8: J7.11@397.49,1115.62 448.98,1115.62 v1(461.49,1103.1) ; R188.2@1943.39,1222.02 v1(1943.39,1257.42)
  SIG1 w6: v1(461.49,1103.1) 436.81,1127.78 436.81,1184.64 460.59,1208.42 505.29,1208.42 508.29,1208.42 514.79,1214.92 514.79,1225.5 521.29,1232 534.29,1232 540.79,1225.5 540.79,1214.92 547.29,1208.42 573.2,1208.42 1294.31,1208.42 1337.63,1165.1 1476.73,1165.1 1502.04,1190.41 1747.99,1190.41 1819.6,1262.02 1819.6,1298.34 1834.68,1313.42 1912.01,1313.42 1943.39,1282.04 v1(1943.39,1257.42)
DBG_SPIB_CS1: J7.37 R215.2 | length 131.3
  Top Layer w8: R215.2@273.38,877.1 301.71,877.1 319.1,859.71 J7.37@397.49,859.71
DBG_SPIB_CS2: J7.39 R324.2 | length 5926.7
  Top Layer w8: J7.39@397.49,840.03 v1@458.81,840.03
  SIG2 w6: v1(459.21,840.03) 409,890.24 409,1921.81 626.15,2138.96 704.28,2138.96 784,2218.68 784,2430.34 808.24,2454.58 808.24,2660.77 998.47,2851 998.47,2926.17 897.28,3027.35 897.28,3418.28 1236,3757 1236,4302.91 1643.95,4710.86 1874.14,4710.86 1891,4694 2158.97,4694 2251.66,4601.31 2594,4601.31 2648.5,4546.81 2648.5,4472.82 2675.51,4445.81 2709,4445.81 v1(2760,4394.81)
  Bottom Layer w8: R324.2@2760,4352.44 v1(2760,4394.81)
DBG_WRMRST: J7.45 R371.2 | length 4630.7
  Top Layer w8: J7.45@397.49,780.97 470.84,780.97 483.36,768.45 v1(483.36,750.36) ; v1(2376,3033.81) 2376,2052.86 2452,1976.86 v1(2452,1639.81)
  SIG1 w6: v1(483.36,750.36) 440.59,707.58 440.59,656.13 597.45,499.27 1409.61,499.27 1839.63,929.3 2081.49,929.3 2375,1222.81 2375,1562.81 v1(2452,1639.81)
  Bottom Layer w8: v1@2376.38,3033.44 2418.82,3075.88 R371.2@2418.82,3251.99
DBG_XREF_CLK0: J7.4 R84.2 | length 152.5
  Top Layer w8: J7.4@623.08,1194.36 674.15,1194.36 692.81,1213.02 692.81,1241.75 704.48,1253.41 R84.2@734.26,1253.41
DSS_UARTA_RX: R160.2 U29.A8 | length 2218.3
  SIG1 w6: v1(1539.43,4350.15) 1488.5,4299.22 1488.5,4053.44 1556.94,3985 1744.14,3985 1806.83,3922.31 1806.83,3895.96 1939,3763.79 1939,3592.25 2110.44,3420.81 2234.81,3420.81 2320,3506 2417.81,3506 2492.64,3431.17 2492.64,3397.17 v1(2516,3373.81)
  Bottom Layer w4: U29.A8@2444.43,3693.52 2444.43,3650.17 2465.59,3629.01 2465.59,3432.33 2494,3403.92 2494,3395.81 v1(2516,3373.81)
  Bottom Layer w8: R160.2@1503.74,4350.15 v1(1539.43,4350.15)
DSS_UARTA_TX: R164.2 U29.A9 | length 2183.2
  SIG1 w6: v1(1562,4301.81) 1500.5,4240.31 1500.5,4061.75 1564.25,3998 1748.11,3998 1824.39,3921.72 1824.39,3902.43 1951,3775.82 1951,3597.22 2050,3498.22 2108.41,3439.81 2236.84,3439.81 2316.84,3519.81 2424.32,3519.81 v1(2556.5,3387.63)
  Bottom Layer w4: U29.A9@2470.03,3693.52 2470.03,3651.44 2484.67,3636.8 2484.67,3459.46 v1(2556.5,3387.63)
  Bottom Layer w8: R164.2@1503.74,4301.11 1504.09,4301.46 1561.65,4301.46 v1(1562,4301.81)
EECLK: R184.1 U18.62 U19.2 | length 305.2
  Top Layer w8: R184.1@914.04,4110.53 943.57,4110.53 948.69,4115.65 U19.2@1000.42,4115.65 1053.71,4115.65 1062.57,4124.51 1062.57,4144.37 v1(1035.47,4171.47)
  Bottom Layer w8: U18.62@1005.4,4091.18 1005.4,4141.4 v1(1035.47,4171.47)
EECS: R187.1 U18.63 U19.1 | length 301.7
  Top Layer w8: v1(996.49,4173.72) 972.16,4198.05 926.82,4198.05 914.04,4185.27 R187.1@914.04,4164.3 937.09,4141.24 U19.1@1000.42,4141.24
  Bottom Layer w8: U18.63@985.72,4091.18 985.72,4162.95 v1(996.49,4173.72)
EEDATA: R201.1 R205.1 U18.61 U19.4 | length 346.5
  Top Layer w8: R201.1@874.67,4006.75 R205.1@874.67,4058.69 ; R205.1@874.67,4059.35 R205.1@874.67,4058.69 ; v1(1026.82,4026.45) 1042.07,4041.69 1042.07,4054.79 1032.39,4064.47 U19.4@1000.42,4064.47 975.65,4064.47 945.72,4034.54 898.81,4034.54 R205.1@874.67,4058.69
  Bottom Layer w8: U18.61@1025.09,4091.18 1025.09,4028.18 v1(1026.82,4026.45)
EMU_TCK: R244.1 R354.1 R375.2 R422.1 | length 2990.9
  Top Layer w8: v1(221.63,1082.03) R422.1@252.91,1082.03 ; v1(248.36,1427.81) 267.36,1408.81 471.22,1408.81 504.34,1441.92 684.4,1441.92 732.29,1489.81 v1(756,1489.81) ; v1(2063.5,1453) 2063.76,1452.74 2107,1452.74 2147.73,1452.74 2233.22,1538.23 2264.02,1538.23 2350.72,1624.94 2431.05,1624.94 2444.88,1611.11 R354.1@2444.88,1577.67
  SIG1 w6: v1(221.63,1082.03) 270.83,1131.24 270.83,1324.57 v1(249.37,1346.03) 229.22,1366.18 229.22,1408.67 v1(248.36,1427.81) ; v1(756,1489.81) 816.78,1489.81 1024.89,1281.7 1345.98,1281.7 1359.95,1295.67 1763.4,1295.67 1817.15,1349.42 1959.92,1349.42 v1(2063.5,1453)
  Bottom Layer w8: v1(248.36,1427.81) R244.1@279.67,1427.81 ; v1(249.37,1346.03) R375.2@280.68,1346.03
EMU_TDI: R356.1 R376.2 R423.1 | length 2960.8
  Top Layer w8: v1(221.63,1050.53) R423.1@252.91,1050.53 ; v1(249.37,1388.1) 264.04,1373.43 505.29,1373.43 554.86,1423 694.56,1423 v1(738.62,1467.06) ; v1(2012.13,1356.52) 2012.13,1295.31 2039.34,1268.1 2083.92,1268.1 2107,1291.18 2150.25,1334.43 2150.25,1374.79 2250.77,1475.31 2279,1475.31 2295.5,1491.81 2295.5,1526.79 2345.72,1577.02 2362.22,1577.02 R356.1@2362.88,1577.67
  SIG1 w6: v1(221.63,1050.53) 221.63,1050.74 283.39,1112.51 283.39,1354.08 v1(249.37,1388.1) ; v1(738.62,1467.06) 821.74,1467.06 1019.1,1269.7 1350.96,1269.7 1361.91,1280.65 1767.97,1280.65 1824.74,1337.42 1993.03,1337.42 v1(2012.13,1356.52)
  Bottom Layer w8: v1(249.37,1388.1) R376.2@280.68,1388.1
EMU_TDO: J19.4 R360.1 R425.2 | length 2868.6
  Top Layer w8: v1(564.31,1385.17) 564.62,1385.47 795.42,1385.47 856.51,1324.39 856.51,1094.79 778.91,1017.19 R425.2@760.24,1017.19 ; v1(2013.63,1263.67) 2013.78,1263.67 2013.78,1235.23 2035.21,1213.81 2379.42,1213.81 2399.67,1234.06 R360.1@2399.67,1271.26
  SIG1 w6: v1(564.31,1385.17) 564.62,1385.47 666.34,1385.47 708.14,1343.67 708.14,1268.53 751.86,1224.81 1323.04,1224.81 1357.44,1259.22 1683.01,1259.22 1705.59,1236.64 1773.77,1236.64 1807.6,1270.47 1807.6,1303.31 1829.71,1325.42 1951.89,1325.42 v1(2013.63,1263.67)
  Bottom Layer w8: v1(564.31,1385.17) 564.42,1385.27 622.98,1385.27 J19.4@623.08,1385.38
EMU_TMS: R358.1 R374.1 R424.2 | length 2145.9
  Top Layer w8: R424.2@760.24,1056 v1(786.39,1056) 787.38,1056 827.32,1095.93 827.32,1312.04 v1(779.8,1359.56) ; R358.1@2317.88,1271.26 R358.1@2317.88,1271.26 2317.94,1246.87 v1(2318,1246.81)
  SIG1 w6: v1(786.39,1056) 786.39,1013.42 806,993.81 1243.53,993.81 1267.53,969.81 2073,969.81 2318,1214.81 v1(2318,1246.81)
  Bottom Layer w8: R374.1@751.09,1359.56 v1(779.8,1359.56)
ERTH_GND: C27.2 C28.2 R119.1 R130.1 R401.2 R419.2
  other v1: 265.38,2156.78 320.78,2156.78 265.38,2212.18 320.78,2212.18 430.82,3037.46 365.05,3070.35 397.94,3070.35 430.82,3070.35
ETH1_INT_PWDN: R224.2 R340.1 U15.44 | length 2539.8
  Top Layer w8: R340.1@1087.72,2935.84 v1(1087.72,2897.4) 1081.96,2891.65 1081.96,2799.29 1102.23,2779.03 1129.14,2779.03 1153.91,2754.26 1153.91,2726.61 1146.4,2719.1 U15.44@1146.4,2699.4
  SIG1 w6: v1(1087.72,2897.4) 1155.7,2965.39 1363.09,2965.39 1380.71,2983 1629.1,2983 1748.91,3102.81 2365.01,3102.81 2429.01,3166.81 2899.99,3166.81 2982,3084.81 3083,3084.81 v1(3084,3083.81)
  Bottom Layer w8: v1(3084,3083.81) 3097.67,3083.83 3120.48,3106.64 R224.2@3120.48,3170.76
ETH1_NRST: R229.2 R342.1 U15.43 | length 2434.6
  Top Layer w8: v1(1143.2,2897.4) R342.1@1143.2,2935.84 ; v1@1166.09,2670.87 U15.43@1166.09,2699.4
  SIG1 w6: v1(1143.2,2897.4) 1312.59,2897.4 1377,2961.81 1624.88,2961.81 1750.88,3087.81 2367,3087.81 2434,3154.81 2889.28,3154.81 v1(2987.21,3056.89)
  SIG2 w6: v1(1143.2,2897.4) 1143.2,2720.76 1166.09,2697.87 v1(1166.09,2670.57)
  Bottom Layer w8: v1(2987.21,3056.89) 2988.24,3055.86 3007.05,3055.86 3018.9,3067.71 R229.2@3018.9,3170.76
ETH2_CLKOUT: R254.1 TP2.1 U4.16 | length 213.1
  Top Layer w8.3: TP2.1@1353,3254.81 1371.39,3273.2 1389.62,3273.2 1407.01,3290.59 1427.66,3290.59 v1(1428.46,3291.39) 1461.58,3291.39 1474.75,3304.56 R254.1@1474.75,3340.36
  Bottom Layer w8: U4.16@1415.57,3261.74 1415.57,3278.51 v1(1428.46,3291.39)
ETH2_INT: R22.1 R34.2 U4.2 | length 2188.1
  SIG1 w6: v1(1182.44,3022.58) 1197.12,3007.9 1275.8,3007.9 1294.73,3026.82 1592.01,3026.82 1681.57,3116.38 2361.61,3116.38 2425.75,3180.52 2908.66,3180.52 2981.37,3107.81 3083,3107.81 v1(3085,3109.81)
  Bottom Layer w8: v1(1182.44,3022.58) v1@1182.57,3022.45 ; v1@1182.57,3022.11 v1@1182.57,3022.45 ; U4.2@1262.03,3088.51 1227.67,3088.51 1207.16,3068 1198.36,3068 R34.2@1182.57,3052.21 v1@1182.57,3022.45 ; v1(3085,3109.81) R22.1@3085,3162.1
ETH2_NRST: R23.1 R46.2 U4.3 | length 1981
  Top Layer w8: R46.2@1182.57,3088.99 1217.48,3088.99 v1(1236.28,3107.79)
  SIG1 w6: v1(1236.28,3107.79) 1305.24,3038.82 1586.99,3038.82 1676.54,3128.38 2356.64,3128.38 2420.78,3192.52 2926.29,3192.52 v1(2985,3133.81)
  Bottom Layer w8: v1(2985,3133.81) R23.1@2984.98,3162.1
  Bottom Layer w10: v1(1236.28,3107.79) 1236.61,3108.12 1261.95,3108.12 U4.3@1262.03,3108.19
ETH2_XI: R242.1 U4.5 | length 81.6
  Bottom Layer w8: R242.1@1182.57,3142.47 1211.91,3142.47 1217,3147.56 U4.5@1262.03,3147.56
ETH2_XO: R246.2 U4.4 | length 88.5
  Bottom Layer w8: R246.2@1182.57,3105.99 1206.41,3105.99 1228.3,3127.88 U4.4@1262.03,3127.88
ETH_CLK_OUT: TP5.1 U15.18 | length 285.8
  Top Layer w8: U15.18@1166.09,2431.68 1166.09,2407.47 1171.49,2402.06 1195.36,2378.19 1195.36,2241.47 1222.74,2214.09 TP5.1@1267.43,2214.09
ETH_GPIO0: R139.1 R143.2 U15.39 | length 126.5
  Top Layer w8: v1(1244.83,2670.57) U15.39@1244.83,2699.1
  Bottom Layer w8: v1(1244.83,2670.57) 1247.11,2672.86 1247.11,2697.56 R139.1@1247.11,2730.45 1247.59,2730.93 R143.2@1284.09,2730.93
ETH_GPIO1: R141.1 R142.2 U15.40 | length 375.5
  Top Layer w8: R141.1@1198.68,2935.84 1229.31,2935.84 1277.72,2887.44 R142.2@1277.72,2843.94 1295.64,2843.94 1313.21,2826.37 1313.21,2775.46 1284.26,2746.51 1238.84,2746.51 1233.22,2741.09 1225.14,2733.02 U15.40@1225.14,2699.4
ETH_LED0: R68.1 R92.1 R97.2 U15.47 | length 1938.1
  Top Layer w6: v1(81.51,2079.45) 101.15,2059.81 246,2059.81 255.87,2069.68 v1(488.06,2069.68)
  Top Layer w8: R97.2@981.5,2842.6 956.9,2842.6 948.66,2834.35 948.66,2766.55 981.65,2733.56 1070.06,2733.56 1087.35,2716.27 U15.47@1087.35,2699.4 ; R97.2@981.5,2846.54 981.5,2880.24 968.47,2893.27 968.47,2898.69 981.5,2911.72 R92.1@981.5,2935.91
  SIG2 w6: v1(488.06,2069.68) 517.37,2069.68 610.64,2162.96 694.34,2162.96 756,2224.62 756,2708 885.28,2837.28 885.28,2849.65 933.11,2897.47 966.97,2897.47 v1(968.47,2895.98)
  Bottom Layer w8: v1(81.51,2079.45) 82.21,2080.15 101.02,2080.15 R68.1@104.25,2076.91
ETH_LED1: R112.1 R113.1 R117.2 R118.2 U15.46 | length 1763.9
  Top Layer w8: R113.1@493.11,3047.15 493.11,2989.5 R112.1@499.02,2983.59 499.02,2965.31 507.22,2957.1 v1(507.22,2956) ; R117.2@603.35,2157.62 R118.2@661.43,2157.62 815.7,2157.62 873,2214.92 v1(873,2215.81) ; U15.46@1107.03,2699.4 v1@1107.03,2727.93
  SIG1 w6: v1(873,2215.81) 912.11,2215.81 1126.47,2430.17 1126.47,2711.49 v1(1107.03,2730.93)
  Bottom Layer w8: v1(507.22,2956) 508.16,2956 516.91,2947.25 873.1,2947.25 1071.3,2749.05 1088.91,2749.05 v1(1107.03,2730.93)
ETH_LED2: R69.2 R132.1 R137.2 U15.45 | length 1087.9
  Top Layer w8: R132.1@1034.65,2935.91 v1(1034.65,2897.47) R137.2@1034.65,2842.6 1051.89,2842.6 1059.46,2835.03 1059.46,2791.82 1094.59,2756.68 1116.54,2756.68 1132.71,2740.52 1132.71,2733.56 1127.8,2728.65 1127.8,2700.48 U15.45@1126.72,2699.4
  SIG1 w6: v1(339.33,2945.62) 393.81,3000.1 932.02,3000.1 v1(1034.65,2897.47)
  Bottom Layer w8: v1(339.33,2945.62) 339.55,2945.84 339.55,2970.18 R69.2@339.78,2970.41
ETH_MDI_CLK: R369.2 U15.16 | length 110.2
  Top Layer w8: 1126.72,2397.9 U15.16@1126.72,2431.68 ; 1126.93,2397.9 1126.93,2384.93 1116.54,2374.54 1116.54,2347.65 R369.2@1132.04,2332.15
ETH_MDI_DATA: R413.2 U15.17 | length 107.8
  Top Layer w8: 1146.4,2415.53 U15.17@1146.4,2431.68 ; 1147.92,2414.01 1148.96,2412.97 1148.96,2354.69 R413.2@1171.49,2332.15
ETH_RBIAS: R337.1 U15.12 | length 109.3
  Top Layer w8: R337.1@948.66,2418.89 987.04,2457.27 U15.12@1042.07,2457.27
ETH_TRD_N: C156.2 R265.1 U4.13 | length 622.4
  Bottom Layer w4.8: U4.13@1356.52,3261.74 1356.52,3278.27 1351.88,3282.91 1351.88,3409.28 1380.18,3437.58 1523.19,3437.58 1541.2,3455.59 1541.2,3546.04 1535.21,3552.02 1511.87,3575.36 1448.09,3575.36 1445.27,3578.17 1445.27,3578.96 1437.83,3586.4 R265.1@1435.86,3586.4 1448.13,3598.67 1454.22,3598.67 C156.2@1474.07,3618.51
ETH_TRD_P: C162.1 R270.1 U4.12 | length 605.6
  Bottom Layer w4.8: U4.12@1336.83,3261.74 1337.31,3262.21 1337.31,3277.42 1341.68,3281.79 1341.68,3413.5 1375.95,3447.78 1518.97,3447.78 1531,3459.81 1531,3541.81 1524.39,3548.42 1507.65,3565.16 1448.09,3565.16 1445.27,3562.35 1445.27,3561.57 1437.83,3554.12 R270.1@1435.86,3554.12 1447.64,3542.34 1453.74,3542.34 C162.1@1474.06,3522.02
ETH_XI: R344.2 U15.15 | length 106.5
  Top Layer w8: R344.2@1083.65,2336.16 1083.65,2374.52 1105.73,2396.6 ; 1105.73,2397.9 1105.73,2396.6 ; U15.15@1107.03,2431.68 1107.03,2397.9 1105.73,2396.6
ETH_XO: R370.2 U15.14 | length 112.3
  Top Layer w8: R370.2@1046.92,2336.16 1046.92,2367.77 1080.32,2401.17 1087.35,2408.19 U15.14@1087.35,2431.68
FB_B1: R14.1 R67.1 U8.3 | length 434.3
  Bottom Layer w8: U8.3@1568.31,1499.12 1612.72,1499.12 1635.65,1522.04 1767.66,1522.04 1887.42,1641.8 1887.42,1658.1 R14.1@1888.29,1658.96 R67.1@1926.84,1658.96
FB_B2: R20.1 R71.1 U8.21 | length 256.1
  Top Layer w8: R20.1@1250.68,1651.64 1289.92,1651.64 R71.1@1290.05,1651.77 1290.05,1617.18 1375.14,1532.08 v1(1375.14,1499.12)
  Bottom Layer w8: v1(1375.14,1499.12) U8.21@1403.94,1499.12
FB_B3: R70.1 R291.1 U8.17 | length 353.7
  Top Layer w8.3: R70.1@1224.04,1327.81 1243.87,1327.81 1254.96,1338.91 1293.67,1338.91 v1(1375.14,1420.38)
  Bottom Layer w8: R291.1@1210.57,1233.19 1210.57,1309.49 1239.99,1338.91 v1(1257.59,1338.91) ; v1(1375.14,1420.38) U8.17@1403.94,1420.38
